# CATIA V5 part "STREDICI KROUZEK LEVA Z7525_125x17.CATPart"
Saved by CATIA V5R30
Part number: STREDICI KROUZEK LEVA Z7525/125x17
Bounding box of the stored display mesh (mm): x -4 to 13, y -62.5 to 62.5, z -62.5 to 62.5
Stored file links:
  C:\Users\ondra\Desktop\PŘÍLOHA P III\CATIA\STREDICI KROUZEK LEVA Z7525_125x17.CATPart
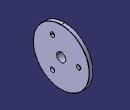
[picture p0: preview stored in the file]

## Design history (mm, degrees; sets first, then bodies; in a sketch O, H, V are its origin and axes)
Set1
  DatumSurface1 to DatumSurface33 "Z7525/12"
  Join1: Elements (DatumSurface1; DatumSurface2; DatumSurface3; DatumSurface4; DatumSurface5; DatumSurface6; DatumSurface7; DatumSurface8; DatumSurface9; DatumSurface10; DatumSurface11; DatumSurface12; DatumSurface13; DatumSurface14; DatumSurface15; DatumSurface16; DatumSurface17; DatumSurface18; DatumSurface19; DatumSurface20; DatumSurface21; DatumSurface22; DatumSurface23; DatumSurface24; DatumSurface25; DatumSurface26; DatumSurface27; DatumSurface28; DatumSurface29; DatumSurface30; DatumSurface31; DatumSurface32; DatumSurface33)
Body1 (main body)
  CloseSurface1: CloseElement Join1
  Sketch1 on yz-plane, origin (0, 0, 0), H (0, 1, 0), V (0, 0, 1)
    circle A1 centre (0, 0) radius 10
    radius A1 = 10
  Pocket1: profile Sketch1, direction (-1, 0, 0), through (limit type 6), opposite side through (limit type 6)
  Plane1: type Offset, RefPlane yz-plane, Offset 7.3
